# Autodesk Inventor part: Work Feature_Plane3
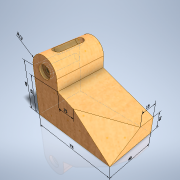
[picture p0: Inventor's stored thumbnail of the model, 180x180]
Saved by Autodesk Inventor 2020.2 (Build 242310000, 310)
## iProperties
Created: 2019-10
Part Number: Work Feature_Plane3
Material: Wood (Cherry)
Document SubType Name: Modeling
Designer: Synergysoft Dell02
Density: 0.63 g/cm^3
Appearance: Cherry - Natural Low Gloss
Author: Synergysoft Dell02
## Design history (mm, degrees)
node "Annotations"
  node "Linear Dimension 1" dims "d0" = 45, "d1" = 26, "d5" = 15, "d36" = 75, "d39" = 15 (derived), "d55" = 35
  node "Linear Dimension 3" dims "d0" = 45, "d1" = 26, "d5" = 15, "d36" = 75, "d45" = 45 (derived), "d55" = 35
  node "Linear Dimension 4" dims "d0" = 45, "d1" = 26, "d5" = 15, "d36" = 75, "d50" = 45 (derived), "d55" = 35
  node "Linear Dimension 5" dims "d0" = 45, "d1" = 26, "d5" = 15, "d36" = 75, "d53" = 75 (derived), "d55" = 35
  node "Linear Dimension 6" dims "d0" = 45, "d1" = 26, "d5" = 15, "d36" = 75, "d54" = 15 (derived), "d55" = 35
  node "Linear Dimension 7" dims "d0" = 45, "d1" = 26, "d5" = 15, "d36" = 75, "d55" = 35, "d57" = 35 (derived)
  node "Linear Dimension 8" dims "d0" = 45, "d1" = 26, "d5" = 15, "d36" = 75, "d55" = 35, "d60" = 15 (derived)
  node "Radial Dimension 1" dims "d0" = 45, "d1" = 26, "d5" = 15, "d36" = 75, "d55" = 35, "d62" = 13 (derived)
sketch "Sketch1"
  geometry: L1 (0, 0)-(0, 45); L2 (0, 45)-(26, 45); L3 (26, 45)-(26, 35); L4 (26, 35)-(75, 15); L5 (75, 15)-(75, 0); L6 (75, 0)-(0, 0); 2 further points
  constraints: 12 end point, 3 perpendicular, 1 midpoint, 1 parallel, 1 vertical, 3 other
  dimensions: "d0" = 45 distance of L1.start L1.end; "d1" = 26 distance of L1.end L2.end; "d5" = 15 distance of L4.end L5.end; "d36" = 75 distance of L5.end L1.start; "d55" = 35 distance from line of L6 L3.end
extrude "Extrusion1" new body sketch "Sketch1" distance "d6" = 45; taper "d7" = 0 deg
workpoint "Work Point4"
workpoint "Work Point2"
  workplane "Work Plane2"
workplane "Work Plane4"
sketch "Sketch6"
  geometry: L1 (0, 12.5)-(0, 32.5); L2 (4, 12.5)-(4, 32.5); L3 (-4, 32.5)-(-4, 12.5); L4 (0, 8.5)-(0, 36.5); L5 (13, 0)-(-13, 0) reference; L6 (-13, 0)-(-13, 45) reference; L7 (13, 45)-(-13, 45) reference; L8 (13, 0)-(13, 45) reference; A1 r 4 centre (0, 12.5) between (-4, 12.5) and (4, 12.5); A2 r 4 centre (0, 32.5) between (4, 32.5) and (-4, 32.5); 3 further points
  constraints: 10 end point, 6 point on circle, 4 midpoint, 4 tangent, 2 centre point, 1 horizontal alignment, 1 parallel, 1 vertical, 1 vertical alignment
  dimensions: "d22" = 8 diameter of A2; "d23" = 20 distance of L1.start L1.end
revolve "Revolution1" sketch "Sketch6" stored, may be unused: angle "d24" = 90 deg
workplane "Work Plane5"
sketch "Sketch7"
  geometry: L1 (83.753, 0.411)-(60.04, 0.186) reference; L2 (5.16, 31.773)-(40.361, 0) reference; L3 (40.361, 0)-(-4.246, -0.422) reference; L4 (-4.246, -0.422)-(5.16, 31.773) reference; L5 (60.04, 0.186)-(62.161, 7.446) reference; A1 r 3.947 centre (80.429, 13.51) between (76.487, 13.719) and (81.295, 9.659) reference; 5 further points; 3 other entities
  constraints: 3 other
extrude "Extrusion3" cut sketch "Sketch7" extent not by distance; stored distance "d25" = 53.786; taper "d26" = 0 deg
workpoint "Work Point3"
  workaxis "Work Axis4"
hole "Hole2" diameter "d29" = 6; stored, may be unused: countersink angle "d33" = 90 deg, drill point angle "d35" = 118 deg; dims "d27" = 10, "d28" = 10, "d30" = 6, "d31" = 12, "d32" = 3, "d34" = 30
body "Solid1"
node "Projected Loop1"
node "Project Cut Edges2"
other parameters: "d21" = 15, "d37" = 0 (derived), "d43" = 0 (derived), "d46" = 0 (derived), "d48" = 0 (derived), "d51" = 0 (derived), "d56" = 3.71304 (derived), "d58" = 0 (derived), "d61" = 24.54351 (derived)
